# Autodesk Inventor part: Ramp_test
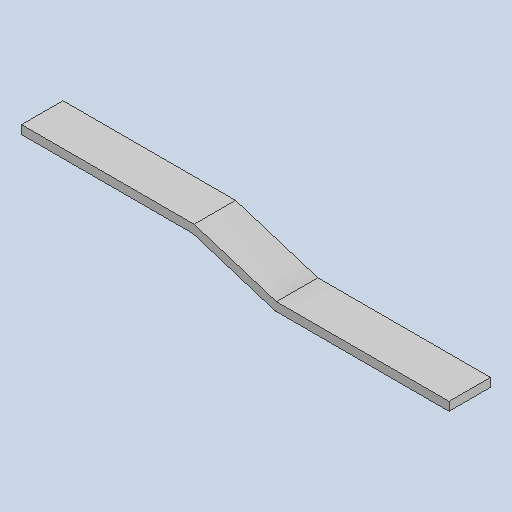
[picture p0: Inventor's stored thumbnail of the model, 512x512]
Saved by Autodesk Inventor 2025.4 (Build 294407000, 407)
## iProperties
Created: 2026-06
Part Number: Ramp_test
Material: Generic
Document SubType Name: Modeling
Designer: AdminForWorker
Density: 1 g/cm^3
Appearance: Default
Title: Ramp_test v10
Author: AdminForWorker
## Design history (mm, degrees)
feature "Body1"
body "Solid1"
